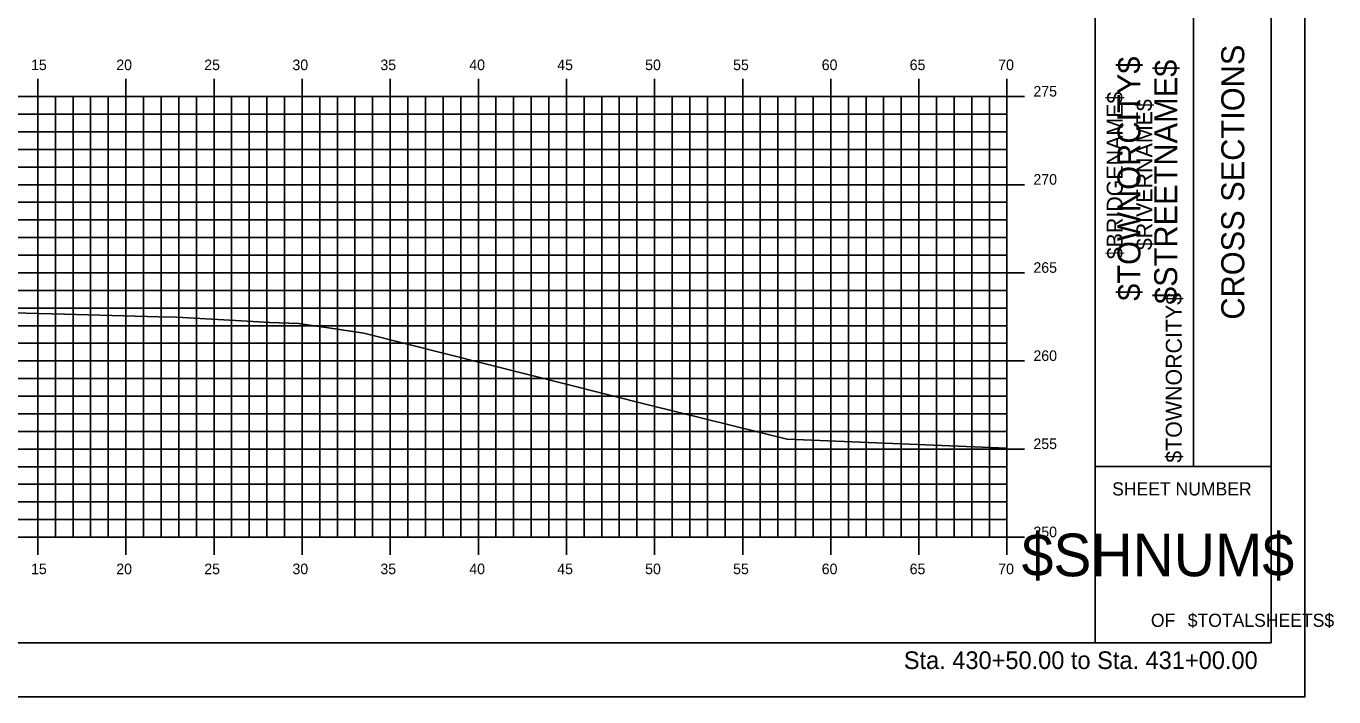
# Model space of a CAD drawing. Extents: x 1168600 to 1177589, y 610178 to 611246.
# Drawn here: x 1175865 to 1175939.2, y 610900.5 to 610938.6 of the extents above; entities that cross this region are included whole.
import ezdxf

# ---------------------------------------------------------------- set-up
doc = ezdxf.new("R2010")
doc.units = 0
for name, color, linetype in [('_Construction', 7, 'Continuous'), ('_Station Equation', 7, 'Continuous'), ('H_V ANNOTATION', 7, 'Continuous'), ('MAJOR', 7, 'Continuous'), ('MINOR', 7, 'Continuous')]:
    doc.layers.add(name, color=color, linetype=linetype)

msp = doc.modelspace()

# ---------------------------------------------------------------- linework, layer by layer
at = {"layer": '_Construction'}
for p, q in [((1175925.663, 610903.599), (1175925.663, 611008.599)), ((1175935.663, 610903.599), (1175935.663, 611008.599)), ((1175931.254, 610913.599), (1175931.254, 610948.599)), ((1175925.663, 610913.599), (1175935.663, 610913.599)), ((1175775.663, 610903.596), (1175935.663, 610903.596))]:
    msp.add_line(p, q, dxfattribs=at)
msp.add_lwpolyline([(1175767.57, 610900.537), (1175937.57, 610900.537), (1175937.57, 611010.537), (1175767.57, 611010.537)], close=True, dxfattribs=at)
at = {"layer": '_Station Equation'}
for points in [[(1175863.506, 610922.349), (1175867.173, 610922.255), (1175868.516, 610922.221), (1175872.524, 610922.103), (1175873.526, 610922.074), (1175877.878, 610921.825), (1175878.536, 610921.787), (1175878.809, 610921.777), (1175880.463, 610921.719), (1175881.242, 610921.606), (1175882.018, 610921.493), (1175884.172, 610921.163), (1175900.305, 610917.106), (1175908.179, 610915.153), (1175920.663, 610914.64)], [(1175863.506, 610922.349), (1175867.174, 610922.255), (1175868.516, 610922.221), (1175872.525, 610922.103), (1175873.526, 610922.074), (1175877.879, 610921.825), (1175878.536, 610921.787), (1175878.809, 610921.777), (1175880.463, 610921.719), (1175881.242, 610921.606), (1175882.018, 610921.493), (1175884.172, 610921.163), (1175900.306, 610917.106), (1175908.179, 610915.153), (1175920.663, 610914.64)]]:
    msp.add_lwpolyline(points, dxfattribs=at)
at = {"layer": 'MAJOR'}
for p, q in [((1175865.663, 610935.598), (1175865.663, 610934.596)), ((1175870.663, 610935.598), (1175870.663, 610934.596)), ((1175875.663, 610935.598), (1175875.663, 610934.596)), ((1175880.663, 610935.598), (1175880.663, 610934.596)), ((1175885.663, 610935.598), (1175885.663, 610934.596)), ((1175890.663, 610935.598), (1175890.663, 610934.596)), ((1175895.663, 610935.598), (1175895.663, 610934.596)), ((1175900.663, 610935.598), (1175900.663, 610934.596)), ((1175905.663, 610935.598), (1175905.663, 610934.596)), ((1175910.663, 610935.598), (1175910.663, 610934.596)), ((1175915.663, 610935.598), (1175915.663, 610934.596)), ((1175920.663, 610935.598), (1175920.663, 610934.596)), ((1175780.663, 610934.596), (1175920.663, 610934.596)), ((1175780.663, 610934.596), (1175920.663, 610934.596)), ((1175865.663, 610909.596), (1175865.663, 610934.596)), ((1175870.663, 610909.596), (1175870.663, 610934.596)), ((1175875.663, 610909.596), (1175875.663, 610934.596)), ((1175880.663, 610909.596), (1175880.663, 610934.596)), ((1175885.663, 610909.596), (1175885.663, 610934.596)), ((1175890.663, 610909.596), (1175890.663, 610934.596)), ((1175895.663, 610909.596), (1175895.663, 610934.596)), ((1175900.663, 610909.596), (1175900.663, 610934.596)), ((1175905.663, 610909.596), (1175905.663, 610934.596)), ((1175910.663, 610909.596), (1175910.663, 610934.596)), ((1175915.663, 610909.596), (1175915.663, 610934.596)), ((1175921.665, 610934.596), (1175919.661, 610934.596)), ((1175920.663, 610909.596), (1175920.663, 610934.596)), ((1175920.663, 610909.596), (1175920.663, 610934.596)), ((1175780.663, 610929.596), (1175920.663, 610929.596)), ((1175921.665, 610929.596), (1175919.661, 610929.596)), ((1175780.663, 610924.596), (1175920.663, 610924.596)), ((1175921.665, 610924.596), (1175919.661, 610924.596)), ((1175780.663, 610919.596), (1175920.663, 610919.596)), ((1175921.665, 610919.596), (1175919.661, 610919.596)), ((1175780.663, 610914.596), (1175920.663, 610914.596)), ((1175921.665, 610914.596), (1175919.661, 610914.596)), ((1175780.663, 610909.596), (1175920.663, 610909.596)), ((1175780.663, 610909.596), (1175920.663, 610909.596)), ((1175865.663, 610908.594), (1175865.663, 610909.596)), ((1175870.663, 610908.594), (1175870.663, 610909.596)), ((1175875.663, 610908.594), (1175875.663, 610909.596)), ((1175880.663, 610908.594), (1175880.663, 610909.596)), ((1175885.663, 610908.594), (1175885.663, 610909.596)), ((1175890.663, 610908.594), (1175890.663, 610909.596)), ((1175895.663, 610908.594), (1175895.663, 610909.596)), ((1175900.663, 610908.594), (1175900.663, 610909.596)), ((1175905.663, 610908.594), (1175905.663, 610909.596)), ((1175910.663, 610908.594), (1175910.663, 610909.596)), ((1175915.663, 610908.594), (1175915.663, 610909.596)), ((1175921.665, 610909.596), (1175919.661, 610909.596)), ((1175920.663, 610908.594), (1175920.663, 610909.596))]:
    msp.add_line(p, q, dxfattribs=at)
at = {"layer": 'MINOR'}
for p, q in [((1175866.663, 610909.596), (1175866.663, 610934.596)), ((1175867.663, 610909.596), (1175867.663, 610934.596)), ((1175868.663, 610909.596), (1175868.663, 610934.596)), ((1175869.663, 610909.596), (1175869.663, 610934.596)), ((1175871.663, 610909.596), (1175871.663, 610934.596)), ((1175872.663, 610909.596), (1175872.663, 610934.596)), ((1175873.663, 610909.596), (1175873.663, 610934.596)), ((1175874.663, 610909.596), (1175874.663, 610934.596)), ((1175876.663, 610909.596), (1175876.663, 610934.596)), ((1175877.663, 610909.596), (1175877.663, 610934.596)), ((1175878.663, 610909.596), (1175878.663, 610934.596)), ((1175879.663, 610909.596), (1175879.663, 610934.596)), ((1175881.663, 610909.596), (1175881.663, 610934.596)), ((1175882.663, 610909.596), (1175882.663, 610934.596)), ((1175883.663, 610909.596), (1175883.663, 610934.596)), ((1175884.663, 610909.596), (1175884.663, 610934.596)), ((1175886.663, 610909.596), (1175886.663, 610934.596)), ((1175887.663, 610909.596), (1175887.663, 610934.596)), ((1175888.663, 610909.596), (1175888.663, 610934.596)), ((1175889.663, 610909.596), (1175889.663, 610934.596)), ((1175891.663, 610909.596), (1175891.663, 610934.596)), ((1175892.663, 610909.596), (1175892.663, 610934.596)), ((1175893.663, 610909.596), (1175893.663, 610934.596)), ((1175894.663, 610909.596), (1175894.663, 610934.596)), ((1175896.663, 610909.596), (1175896.663, 610934.596)), ((1175897.663, 610909.596), (1175897.663, 610934.596)), ((1175898.663, 610909.596), (1175898.663, 610934.596)), ((1175899.663, 610909.596), (1175899.663, 610934.596)), ((1175901.663, 610909.596), (1175901.663, 610934.596)), ((1175902.663, 610909.596), (1175902.663, 610934.596)), ((1175903.663, 610909.596), (1175903.663, 610934.596)), ((1175904.663, 610909.596), (1175904.663, 610934.596)), ((1175906.663, 610909.596), (1175906.663, 610934.596)), ((1175907.663, 610909.596), (1175907.663, 610934.596)), ((1175908.663, 610909.596), (1175908.663, 610934.596)), ((1175909.663, 610909.596), (1175909.663, 610934.596)), ((1175911.663, 610909.596), (1175911.663, 610934.596)), ((1175912.663, 610909.596), (1175912.663, 610934.596)), ((1175913.663, 610909.596), (1175913.663, 610934.596)), ((1175914.663, 610909.596), (1175914.663, 610934.596)), ((1175916.663, 610909.596), (1175916.663, 610934.596)), ((1175917.663, 610909.596), (1175917.663, 610934.596)), ((1175918.663, 610909.596), (1175918.663, 610934.596)), ((1175919.663, 610909.596), (1175919.663, 610934.596)), ((1175780.663, 610933.596), (1175920.663, 610933.596)), ((1175920.663, 610933.596), (1175919.661, 610933.596)), ((1175780.663, 610932.596), (1175920.663, 610932.596)), ((1175920.663, 610932.596), (1175919.661, 610932.596)), ((1175780.663, 610931.596), (1175920.663, 610931.596)), ((1175920.663, 610931.596), (1175919.661, 610931.596)), ((1175780.663, 610930.596), (1175920.663, 610930.596)), ((1175920.663, 610930.596), (1175919.661, 610930.596)), ((1175780.663, 610928.596), (1175920.663, 610928.596)), ((1175920.663, 610928.596), (1175919.661, 610928.596)), ((1175780.663, 610927.596), (1175920.663, 610927.596)), ((1175920.663, 610927.596), (1175919.661, 610927.596)), ((1175780.663, 610926.596), (1175920.663, 610926.596)), ((1175920.663, 610926.596), (1175919.661, 610926.596)), ((1175780.663, 610925.596), (1175920.663, 610925.596)), ((1175920.663, 610925.596), (1175919.661, 610925.596)), ((1175780.663, 610923.596), (1175920.663, 610923.596)), ((1175920.663, 610923.596), (1175919.661, 610923.596)), ((1175780.663, 610922.596), (1175920.663, 610922.596)), ((1175920.663, 610922.596), (1175919.661, 610922.596)), ((1175780.663, 610921.596), (1175920.663, 610921.596)), ((1175920.663, 610921.596), (1175919.661, 610921.596)), ((1175780.663, 610920.596), (1175920.663, 610920.596)), ((1175920.663, 610920.596), (1175919.661, 610920.596)), ((1175780.663, 610918.596), (1175920.663, 610918.596)), ((1175920.663, 610918.596), (1175919.661, 610918.596)), ((1175780.663, 610917.596), (1175920.663, 610917.596)), ((1175920.663, 610917.596), (1175919.661, 610917.596)), ((1175780.663, 610916.596), (1175920.663, 610916.596)), ((1175920.663, 610916.596), (1175919.661, 610916.596)), ((1175780.663, 610915.596), (1175920.663, 610915.596)), ((1175920.663, 610915.596), (1175919.661, 610915.596)), ((1175780.663, 610913.596), (1175920.663, 610913.596)), ((1175920.663, 610913.596), (1175919.661, 610913.596)), ((1175780.663, 610912.596), (1175920.663, 610912.596)), ((1175920.663, 610912.596), (1175919.661, 610912.596)), ((1175780.663, 610911.596), (1175920.663, 610911.596)), ((1175920.663, 610911.596), (1175919.661, 610911.596)), ((1175780.663, 610910.596), (1175920.663, 610910.596)), ((1175920.663, 610910.596), (1175919.661, 610910.596))]:
    msp.add_line(p, q, dxfattribs=at)

# ---------------------------------------------------------------- texts
at = {"layer": '_Construction'}
for s, height, rotation, p in [('$TOWNORCITY$', 1.30428, 90, (1175928.235, 610923.007)), ('CROSS SECTIONS', 1.30428, 90, (1175934.128, 610921.938)), ('$STREETNAME$', 1.30428, 90, (1175930.322, 610922.827)), ('$BRIDGENAME$', 0.90716, 90, (1175927.229, 610925.367)), ('$RIVERNAME$', 0.90716, 90, (1175928.906, 610925.882)), ('$TOWNORCITY$', 0.90716, 90, (1175930.583, 610913.82)), ('SHEET NUMBER', 0.74527, 360, (1175926.629, 610911.963)), ('$SHNUM$', 2.4194, 360, (1175921.496, 610907.379)), ('OF', 0.7453, 360, (1175928.83, 610904.509)), ('$TOTALSHEETS$', 0.74527, 360, (1175930.92, 610904.509))]:
    msp.add_text(s, height=height, rotation=rotation, dxfattribs=at).set_placement(p)
at = {"layer": 'H_V ANNOTATION'}
for s, height, p in [('15', 0.6, (1175865.28, 610936.096)), ('20', 0.6, (1175870.117, 610936.096)), ('25', 0.6, (1175875.109, 610936.096)), ('30', 0.6, (1175880.112, 610936.096)), ('35', 0.6, (1175885.104, 610936.096)), ('40', 0.6, (1175890.149, 610936.096)), ('45', 0.6, (1175895.141, 610936.096)), ('50', 0.6, (1175900.128, 610936.096)), ('55', 0.6, (1175905.12, 610936.096)), ('60', 0.6, (1175910.149, 610936.096)), ('65', 0.6, (1175915.141, 610936.096)), ('70', 0.6, (1175920.165, 610936.096)), ('275', 0.6, (1175922.163, 610934.596)), ('270', 0.6, (1175922.163, 610929.596)), ('265', 0.6, (1175922.163, 610924.596)), ('260', 0.6, (1175922.163, 610919.596)), ('255', 0.6, (1175922.163, 610914.596)), ('250', 0.6, (1175922.163, 610909.596)), ('15', 0.6, (1175865.28, 610907.496)), ('20', 0.6, (1175870.117, 610907.496)), ('25', 0.6, (1175875.109, 610907.496)), ('30', 0.6, (1175880.112, 610907.496)), ('35', 0.6, (1175885.104, 610907.496)), ('40', 0.6, (1175890.149, 610907.496)), ('45', 0.6, (1175895.141, 610907.496)), ('50', 0.6, (1175900.128, 610907.496)), ('55', 0.6, (1175905.12, 610907.496)), ('60', 0.6, (1175910.149, 610907.496)), ('65', 0.6, (1175915.141, 610907.496)), ('70', 0.6, (1175920.165, 610907.496)), ('Sta. 430+50.00 to Sta. 431+00.00', 1.0002, (1175914.809, 610902.116))]:
    msp.add_text(s, height=height, dxfattribs=at).set_placement(p)

doc.saveas('drawing.dxf')
